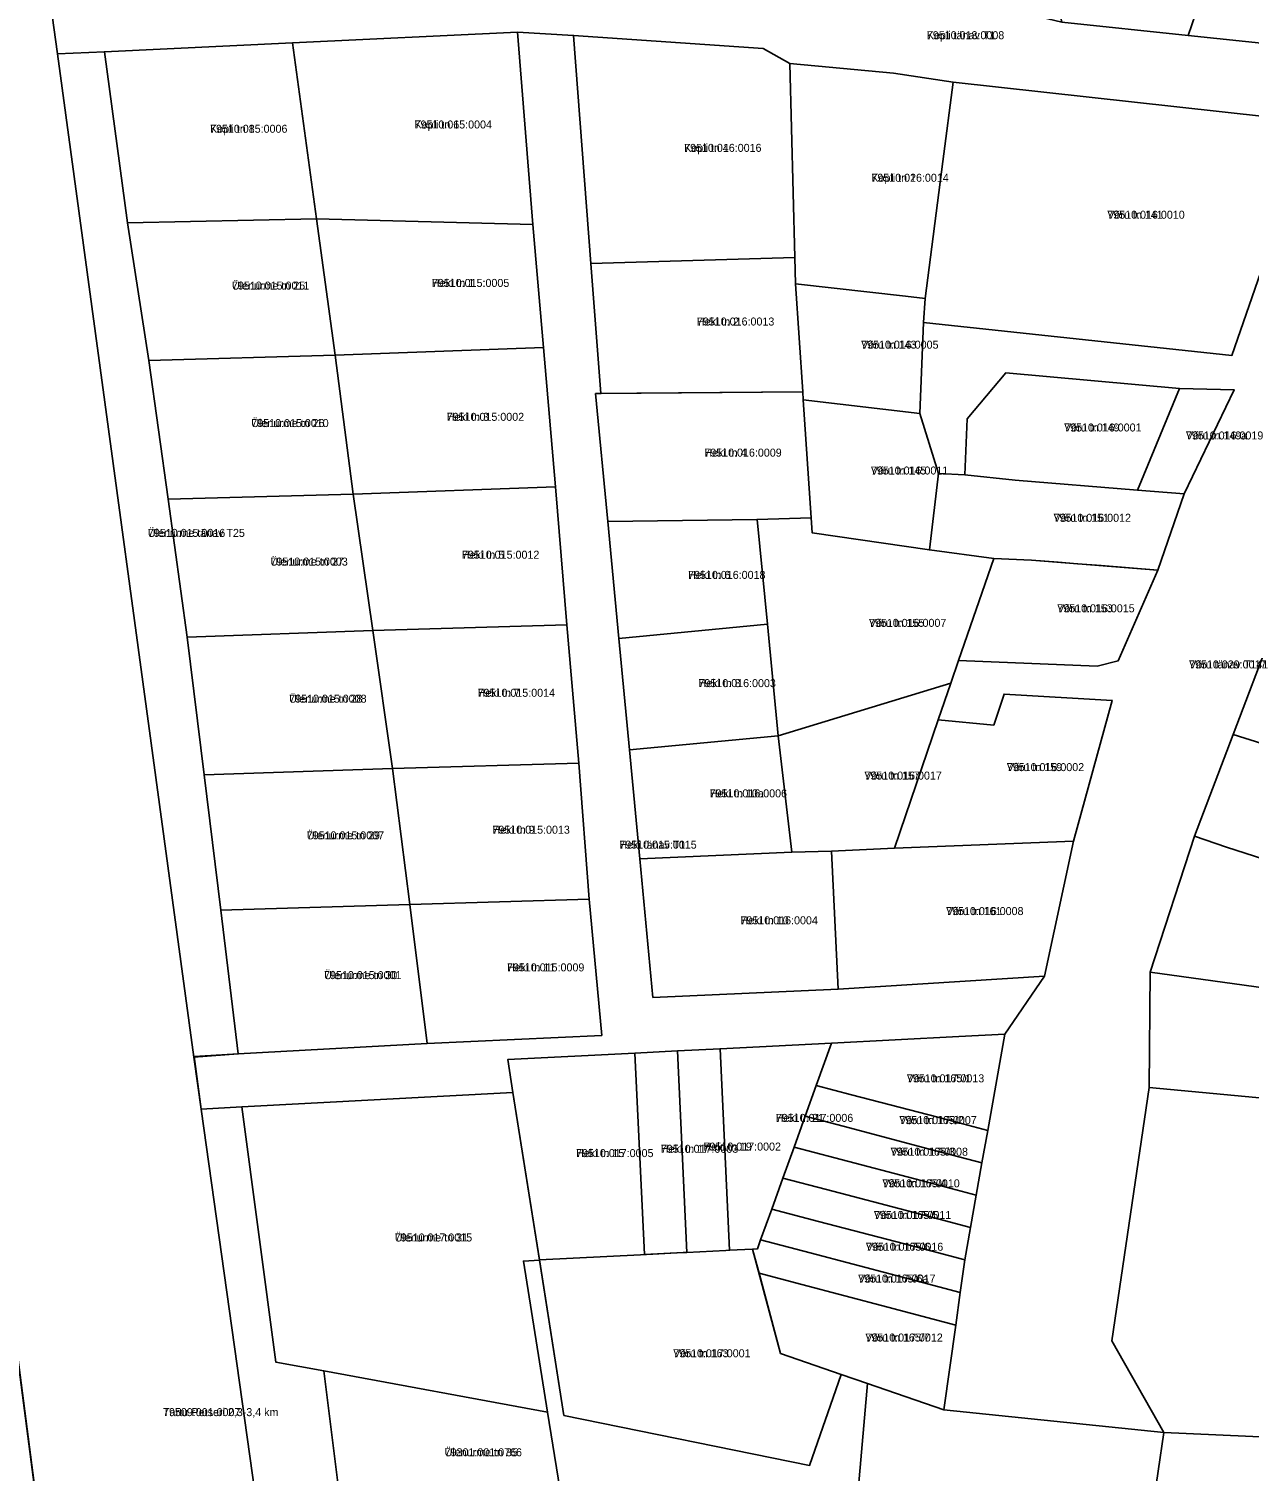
# Model space of a CAD drawing. Extents: x 643847 to 663718, y 6468443 to 6482775.
# Drawn here: x 658757.8 to 658986.5, y 6470500.7 to 6470771 of the extents above; entities that cross this region are included whole.
import ezdxf

# ---------------------------------------------------------------- set-up
doc = ezdxf.new("R2010")
doc.units = 0
for name, color, linetype in [('L_AADRESS', 7, 'Continuous'), ('PIIR', 7, 'Continuous'), ('TUNNUS', 7, 'Continuous')]:
    doc.layers.add(name, color=color, linetype=linetype)

msp = doc.modelspace()

# ---------------------------------------------------------------- linework, layer by layer
at = {"layer": 'PIIR'}
for points in [[(658746.57, 6470967.46), (658748.37, 6470894.81), (658754.88, 6470826.54), (658761.21, 6470780.3), (658763.13, 6470766.29), (658788.68, 6470578.29), (658790.04, 6470568.54), (658806.39, 6470452.3), (658813.68, 6470400.13), (658772.48, 6470401.58), (658771.32, 6470401.59), (658754.4, 6470532.15), (658753.48, 6470542.45), (658748.57, 6470576.12), (658744.35, 6470609.28), (658742.02, 6470624.21), (658737.79, 6470658.27), (658733.34, 6470692.38), (658735.49, 6470707.87), (658715.37, 6470870.27), (658711.74, 6470952.85)], [(658990.76, 6470657.95), (658983.48, 6470638.76), (658976.24, 6470619.67), (658967.89, 6470594.21), (658967.73, 6470572.59), (658960.73, 6470525.08), (658970.5, 6470507.92), (658929.25, 6470512.17), (658931.46, 6470528.06), (658932.31, 6470534.16), (658933.16, 6470540.27), (658934.25, 6470546.35), (658935.32, 6470552.41), (658936.39, 6470558.46), (658937.47, 6470564.52), (658940.67, 6470582.59), (658948.1, 6470593.43), (658953.57, 6470618.75), (658960.81, 6470645.13), (658940.53, 6470646.29), (658938.61, 6470640.5), (658928.18, 6470641.51), (658930.53, 6470648.32), (658931.99, 6470652.57), (658957.95, 6470651.55), (658961.92, 6470652.55), (658969.33, 6470669.51), (658974.27, 6470683.8), (658983.67, 6470703.3), (658973.39, 6470703.57), (658940.84, 6470706.48), (658933.6, 6470697.88), (658933.2, 6470687.37), (658928.25, 6470687.66), (658924.72, 6470698.9), (658925.46, 6470715.92), (658976.23, 6470710.52), (658983.22, 6470709.77), (658998.39, 6470753.53)], [(659005.71, 6470569), (658967.73, 6470572.59), (658967.89, 6470594.21), (659003.14, 6470589.35)]]:
    msp.add_lwpolyline(points, dxfattribs=at)
for points in [[(658956.87, 6470797.9), (658973.43, 6470792.25), (658974.24, 6470794.62), (658982.56, 6470791.78), (658975.03, 6470769.73), (658951.36, 6470772.19), (658950.02, 6470777.84)], [(659003.09, 6470766.8), (658975.03, 6470769.73), (658982.56, 6470791.78), (658983.85, 6470795.56), (659009.88, 6470786.67)], [(658839.94, 6470784.5), (658932.96, 6470776.66), (658951.36, 6470772.19), (658975.03, 6470769.73), (659003.09, 6470766.8), (658998.39, 6470753.53), (658930.96, 6470760.99), (658919.79, 6470762.66), (658900.37, 6470764.47), (658895.41, 6470767.26), (658859.85, 6470769.74), (658849.31, 6470770.31), (658807.18, 6470768.34), (658771.92, 6470766.68), (658763.13, 6470766.29), (658761.21, 6470780.3), (658777.32, 6470781.36), (658804.6, 6470783.22)], [(658807.18, 6470768.34), (658811.64, 6470735.37), (658776.28, 6470734.63), (658771.92, 6470766.68)], [(658852.19, 6470734.27), (658849.31, 6470770.31), (658859.85, 6470769.74), (658863.11, 6470727.01), (658864.98, 6470702.62), (658863.97, 6470702.6), (658866.25, 6470678.65), (658868.33, 6470656.73), (658870.33, 6470635.83), (658872.25, 6470615.41), (658874.72, 6470589.47), (658909.41, 6470591.03), (658948.1, 6470593.43), (658940.67, 6470582.59), (658932.08, 6470582.14), (658908.2, 6470580.91), (658887.31, 6470579.84), (658879.32, 6470579.44), (658871.33, 6470579.03), (658847.52, 6470577.81), (658848.48, 6470571.62), (658797.68, 6470568.93), (658790.04, 6470568.54), (658788.74, 6470578.42), (658797, 6470578.89), (658832.41, 6470580.81), (658865.12, 6470582.34), (658862.79, 6470607.88), (658860.83, 6470633.39), (658858.6, 6470659.27), (658856.45, 6470685.12), (658854.19, 6470711.23)], [(658852.19, 6470734.27), (658811.64, 6470735.37), (658807.18, 6470768.34), (658849.31, 6470770.31)], [(658859.85, 6470769.74), (658895.41, 6470767.26), (658900.37, 6470764.47), (658901.29, 6470728.12), (658863.11, 6470727.01)], [(658776.28, 6470734.63), (658780.22, 6470708.82), (658783.85, 6470682.86), (658787.46, 6470656.98), (658790.61, 6470631.17), (658793.71, 6470605.82), (658797, 6470578.89), (658788.68, 6470578.29), (658763.13, 6470766.29), (658771.92, 6470766.68)], [(658919.79, 6470762.66), (658930.96, 6470760.99), (658929.04, 6470746.11), (658925.74, 6470720.46), (658922.04, 6470720.86), (658901.41, 6470723.16), (658901.29, 6470728.12), (658900.37, 6470764.47)], [(658930.96, 6470760.99), (658998.39, 6470753.53), (658983.22, 6470709.77), (658976.23, 6470710.52), (658925.46, 6470715.92), (658925.74, 6470720.46), (658929.04, 6470746.11)], [(658776.28, 6470734.63), (658811.64, 6470735.37), (658815.17, 6470709.83), (658780.22, 6470708.82)], [(658854.19, 6470711.23), (658815.17, 6470709.83), (658811.64, 6470735.37), (658852.19, 6470734.27)], [(658863.11, 6470727.01), (658901.29, 6470728.12), (658901.41, 6470723.16), (658902.79, 6470702.95), (658864.98, 6470702.62)], [(658925.46, 6470715.92), (658924.72, 6470698.9), (658902.88, 6470701.45), (658902.79, 6470702.95), (658901.41, 6470723.16), (658922.04, 6470720.86), (658925.74, 6470720.46)], [(658780.22, 6470708.82), (658815.17, 6470709.83), (658818.57, 6470683.78), (658783.85, 6470682.86)], [(658856.45, 6470685.12), (658818.57, 6470683.78), (658815.17, 6470709.83), (658854.19, 6470711.23)], [(658965.54, 6470684.53), (658942.59, 6470686.39), (658933.2, 6470687.37), (658933.6, 6470697.88), (658940.84, 6470706.48), (658973.4, 6470703.57)], [(658973.39, 6470703.57), (658983.67, 6470703.3), (658974.27, 6470683.8), (658965.54, 6470684.51)], [(658863.97, 6470702.6), (658902.79, 6470702.95), (658902.88, 6470701.45), (658904.38, 6470679.32), (658894.25, 6470679.05), (658866.25, 6470678.65)], [(658928.25, 6470687.66), (658926.53, 6470673.33), (658904.55, 6470676.53), (658904.38, 6470679.32), (658902.88, 6470701.45), (658924.72, 6470698.9)], [(658969.33, 6470669.51), (658945.69, 6470671.41), (658938.58, 6470671.72), (658926.53, 6470673.33), (658928.25, 6470687.66), (658933.2, 6470687.37), (658942.59, 6470686.39), (658965.54, 6470684.53), (658974.27, 6470683.82)], [(658858.6, 6470659.27), (658822.21, 6470658.21), (658818.57, 6470683.78), (658856.45, 6470685.12)], [(658783.85, 6470682.86), (658818.57, 6470683.78), (658822.21, 6470658.21), (658787.46, 6470656.98)], [(658868.33, 6470656.73), (658866.25, 6470678.65), (658894.25, 6470679.05), (658896.2, 6470659.39)], [(658896.2, 6470659.39), (658894.25, 6470679.05), (658904.38, 6470679.32), (658904.55, 6470676.53), (658926.53, 6470673.33), (658938.58, 6470671.72), (658931.99, 6470652.57), (658930.53, 6470648.32), (658898.19, 6470638.49)], [(658961.92, 6470652.55), (658957.95, 6470651.55), (658931.99, 6470652.57), (658938.58, 6470671.72), (658945.69, 6470671.41), (658950.69, 6470671.01), (658954.26, 6470670.73), (658958.72, 6470670.37), (658969.33, 6470669.51)], [(658787.46, 6470656.98), (658822.21, 6470658.21), (658825.89, 6470632.34), (658790.61, 6470631.17)], [(658860.83, 6470633.39), (658825.89, 6470632.34), (658822.21, 6470658.21), (658858.6, 6470659.27)], [(658868.33, 6470656.73), (658896.2, 6470659.39), (658898.19, 6470638.49), (658870.33, 6470635.83)], [(658990.76, 6470657.95), (658995.52, 6470656.42), (659023.17, 6470647.5), (659022.03, 6470644.2), (659016.46, 6470628.13), (658988.85, 6470637.03), (658983.48, 6470638.76)], [(658900.73, 6470616.69), (658898.19, 6470638.49), (658930.53, 6470648.32), (658928.18, 6470641.51), (658920, 6470617.45), (658908.19, 6470616.85)], [(658953.57, 6470618.75), (658920, 6470617.45), (658928.18, 6470641.51), (658938.61, 6470640.5), (658940.53, 6470646.29), (658960.81, 6470645.13)], [(658870.33, 6470635.83), (658898.19, 6470638.49), (658900.73, 6470616.69), (658872.25, 6470615.41)], [(658983.48, 6470638.76), (658988.85, 6470637.03), (659016.46, 6470628.13), (659014.23, 6470621.5), (659009.8, 6470608.74), (658982.2, 6470617.64), (658976.24, 6470619.67)], [(658862.79, 6470607.88), (658829.14, 6470606.89), (658825.89, 6470632.34), (658860.83, 6470633.39)], [(658790.61, 6470631.17), (658825.89, 6470632.34), (658829.14, 6470606.89), (658793.71, 6470605.82)], [(658976.24, 6470619.67), (658982.2, 6470617.64), (659009.8, 6470608.74), (659003.14, 6470589.35), (658967.89, 6470594.21)], [(658872.25, 6470615.41), (658900.73, 6470616.69), (658908.19, 6470616.85), (658909.41, 6470591.03), (658874.72, 6470589.47)], [(658948.1, 6470593.43), (658909.41, 6470591.03), (658908.19, 6470616.85), (658920, 6470617.45), (658953.57, 6470618.75)], [(658793.71, 6470605.82), (658829.14, 6470606.89), (658832.41, 6470580.81), (658797, 6470578.89)], [(658865.12, 6470582.34), (658832.41, 6470580.81), (658829.14, 6470606.89), (658862.79, 6470607.88)], [(658940.67, 6470582.59), (658937.47, 6470564.52), (658928.09, 6470567.01), (658911.92, 6470571.23), (658905.34, 6470572.98), (658908.2, 6470580.91), (658932.08, 6470582.14)], [(658871.33, 6470579.03), (658873.12, 6470541.27), (658872.42, 6470541.24), (658853.44, 6470540.27), (658848.48, 6470571.62), (658847.52, 6470577.81)], [(658879.32, 6470579.44), (658881.1, 6470541.68), (658880.41, 6470541.64), (658873.12, 6470541.27), (658871.33, 6470579.03)], [(658887.31, 6470579.84), (658889.1, 6470542.09), (658888.4, 6470542.05), (658881.1, 6470541.68), (658879.32, 6470579.44)], [(658908.2, 6470580.91), (658905.34, 6470572.98), (658903.26, 6470567.19), (658901.17, 6470561.4), (658899.09, 6470555.61), (658897, 6470549.81), (658894.91, 6470544.01), (658894.32, 6470542.36), (658893.39, 6470542.3), (658889.1, 6470542.09), (658887.31, 6470579.84)], [(658797.68, 6470568.93), (658848.48, 6470571.62), (658853.44, 6470540.25), (658850.45, 6470540.04), (658854.99, 6470511.73), (658813.03, 6470519.46), (658804.03, 6470521.12)], [(658936.39, 6470558.46), (658926.53, 6470561.05), (658910.39, 6470565.32), (658903.26, 6470567.19), (658905.34, 6470572.98), (658911.92, 6470571.23), (658928.09, 6470567.01), (658937.47, 6470564.52)], [(659005.71, 6470569), (659004.92, 6470560.64), (659014.43, 6470559.74), (659015.22, 6470568.11), (659026.08, 6470567.08), (659021.44, 6470529.27), (659017.75, 6470505.82), (658970.5, 6470507.92), (658960.73, 6470525.08), (658967.73, 6470572.59)], [(658804.03, 6470521.12), (658813.03, 6470519.46), (658817.06, 6470487.49), (658858.62, 6470488.95), (658890, 6470490.35), (658883.39, 6470438.13), (658878.28, 6470439.07), (658806.39, 6470452.3), (658790.04, 6470568.54), (658797.68, 6470568.93)], [(658935.32, 6470552.41), (658924.97, 6470555.13), (658908.83, 6470559.38), (658901.17, 6470561.4), (658903.26, 6470567.19), (658910.39, 6470565.32), (658926.53, 6470561.05), (658936.39, 6470558.46)], [(658934.25, 6470546.35), (658923.4, 6470549.2), (658907.28, 6470553.46), (658899.09, 6470555.61), (658901.17, 6470561.4), (658908.83, 6470559.38), (658924.97, 6470555.13), (658935.32, 6470552.41)], [(658921.84, 6470543.26), (658905.72, 6470547.5), (658897, 6470549.81), (658899.09, 6470555.61), (658907.28, 6470553.46), (658923.4, 6470549.2), (658934.25, 6470546.35), (658933.16, 6470540.27)], [(658897, 6470549.81), (658905.72, 6470547.5), (658921.84, 6470543.26), (658933.16, 6470540.27), (658932.31, 6470534.16), (658920.28, 6470537.33), (658904.17, 6470541.57), (658894.91, 6470544.01)], [(658893.39, 6470542.29), (658894.31, 6470542.34), (658894.91, 6470544.01), (658904.17, 6470541.57), (658920.28, 6470537.33), (658932.31, 6470534.16), (658931.46, 6470528.05), (658918.72, 6470531.4), (658902.62, 6470535.64), (658894.61, 6470537.76)], [(658904.09, 6470501.75), (658858.04, 6470511.13), (658853.44, 6470540.27), (658872.42, 6470541.24), (658880.41, 6470541.64), (658881.1, 6470541.68), (658888.4, 6470542.05), (658889.1, 6470542.09), (658893.39, 6470542.3), (658898.66, 6470522.74), (658909.99, 6470518.82)], [(658912.69, 6470491.37), (658890, 6470490.35), (658858.62, 6470488.95), (658854.99, 6470511.73), (658850.45, 6470540.04), (658853.44, 6470540.25), (658858.04, 6470511.13), (658904.09, 6470501.75), (658909.99, 6470518.82), (658914.95, 6470517.11)], [(658929.25, 6470512.17), (658914.95, 6470517.11), (658909.99, 6470518.82), (658898.66, 6470522.74), (658894.61, 6470537.78), (658902.62, 6470535.66), (658918.72, 6470531.42), (658931.46, 6470528.06)], [(658754.31, 6470532.24), (658771.32, 6470401.57), (658652.18, 6470398.91), (658647.27, 6470431.68), (658699.05, 6470440.41), (658694.89, 6470480.89), (658641.17, 6470477.78), (658632.97, 6470526.78)], [(658858.62, 6470488.95), (658817.06, 6470487.49), (658813.03, 6470519.46), (658854.99, 6470511.73)], [(658912.69, 6470491.37), (658914.95, 6470517.11), (658929.25, 6470512.17), (658970.5, 6470507.92), (658968.33, 6470493.45), (658959.37, 6470433.88), (658958.07, 6470399.38), (658956.21, 6470350.25), (658929.13, 6470182.89), (658908.15, 6470192.43), (658907.56, 6470204.71), (658907.05, 6470227.38), (658906.76, 6470240.09), (658901.62, 6470307.58), (658910.37, 6470376.7), (658914.67, 6470410.49), (658917.39, 6470431.87)], [(659015.01, 6470488.43), (659038.14, 6470485.66), (659052.34, 6470484.05), (659083, 6470486.1), (659081.79, 6470476.89), (659005.22, 6470476.43), (658992.85, 6470488.52), (658968.33, 6470493.45), (658970.5, 6470507.92), (659017.75, 6470505.82)]]:
    msp.add_lwpolyline(points, close=True, dxfattribs=at)

# ---------------------------------------------------------------- texts
at = {"layer": 'L_AADRESS'}
for s, p in [('Kopli tänav T1', (658926.06, 6470769.02)), ('Kopli tn 8', (658791.72, 6470751.49)), ('Kopli tn 6', (658830.05, 6470752.29)), ('Kopli tn 4', (658880.57, 6470747.91)), ('Kopli tn 2', (658915.66, 6470742.31)), ('Võru tn 141', (658959.88, 6470735.38)), ('Ülenurme tn 25', (658795.83, 6470722.1)), ('Heki tn 1', (658833.3, 6470722.6)), ('Heki tn 2', (658882.97, 6470715.37)), ('Võru tn 143', (658913.74, 6470711.03)), ('Ülenurme tn 26', (658799.45, 6470696.34)), ('Heki tn 3', (658836.08, 6470697.51)), ('Võru tn 149', (658951.79, 6470695.51)), ('Võru tn 149a', (658974.61, 6470694.02)), ('Heki tn 4', (658884.35, 6470690.8)), ('Võru tn 145', (658915.57, 6470687.45)), ('Võru tn 151', (658949.81, 6470678.59)), ('Ülenurme tänav T25', (658780.07, 6470675.76)), ('Ülenurme tn 27', (658803.03, 6470670.38)), ('Heki tn 5', (658838.93, 6470671.67)), ('Heki tn 6', (658881.31, 6470667.89)), ('Võru tn 153', (658950.5, 6470661.63)), ('Võru tn 155', (658915.21, 6470658.9)), ('Võru tänav T141', (658975.2, 6470651.11)), ('Ülenurme tn 28', (658806.55, 6470644.69)), ('Heki tn 7', (658841.87, 6470645.8)), ('Heki tn 8', (658883.26, 6470647.61)), ('Võru tn 159', (658941.04, 6470631.87)), ('Võru tn 157', (658914.36, 6470630.28)), ('Heki tn 10a', (658885.35, 6470626.95)), ('Ülenurme tn 29', (658809.84, 6470619.08)), ('Heki tn 9', (658844.65, 6470620.14)), ('Heki tänav T1', (658868.42, 6470617.34)), ('Võru tn 161', (658929.67, 6470604.89)), ('Heki tn 10', (658891.13, 6470603.16)), ('Heki tn 11', (658847.37, 6470594.34)), ('Ülenurme tn 30', (658813.09, 6470592.89)), ('Võru tn 165/1', (658922.31, 6470573.55)), ('Heki tn 21', (658897.76, 6470566.14)), ('Võru tn 165/2', (658920.91, 6470565.72)), ('Heki tn 15', (658860.32, 6470559.54)), ('Heki tn 17', (658876.21, 6470560.35)), ('Heki tn 19', (658884.21, 6470560.76)), ('Võru tn 165/3', (658919.26, 6470559.8)), ('Võru tn 165/4', (658917.72, 6470553.88)), ('Võru tn 165/5', (658916.13, 6470547.94)), ('Ülenurme tn 31', (658826.34, 6470543.73)), ('Võru tn 165/6', (658914.63, 6470541.99)), ('Võru tn 165/6a', (658913.18, 6470536.03)), ('Võru tn 165/7', (658914.54, 6470524.98)), ('Võru tn 163', (658878.52, 6470522.03)), ('Tartu-Petseri 2,3-3,4 km', (658782.91, 6470511)), ('Ülenurme tn 35', (658835.68, 6470503.48))]:
    msp.add_text(s, height=1.5, dxfattribs=at).set_placement(p)
at = {"layer": 'TUNNUS'}
for s, p in [('79510:013:0008', (658926.06, 6470769.02)), ('79510:015:0006', (658791.72, 6470751.49)), ('79510:015:0004', (658830.05, 6470752.29)), ('79510:016:0016', (658880.57, 6470747.91)), ('79510:016:0014', (658915.66, 6470742.31)), ('79510:016:0010', (658959.88, 6470735.38)), ('79510:015:0011', (658795.83, 6470722.1)), ('79510:015:0005', (658833.3, 6470722.6)), ('79510:016:0013', (658882.97, 6470715.37)), ('79510:016:0005', (658913.74, 6470711.03)), ('79510:015:0010', (658799.45, 6470696.34)), ('79510:015:0002', (658836.08, 6470697.51)), ('79510:016:0001', (658951.79, 6470695.51)), ('79510:016:0019', (658974.61, 6470694.02)), ('79510:016:0009', (658884.35, 6470690.8)), ('79510:016:0011', (658915.57, 6470687.45)), ('79510:016:0012', (658949.81, 6470678.59)), ('79510:015:0016', (658780.07, 6470675.76)), ('79510:015:0003', (658803.03, 6470670.38)), ('79510:015:0012', (658838.93, 6470671.67)), ('79510:016:0018', (658881.31, 6470667.89)), ('79510:016:0015', (658950.5, 6470661.63)), ('79510:016:0007', (658915.21, 6470658.9)), ('79510:029:0017', (658975.2, 6470651.11)), ('79510:015:0014', (658841.87, 6470645.8)), ('79510:016:0003', (658883.26, 6470647.61)), ('79510:015:0008', (658806.55, 6470644.69)), ('79510:016:0002', (658941.04, 6470631.87)), ('79510:016:0017', (658914.36, 6470630.28)), ('79510:016:0006', (658885.35, 6470626.95)), ('79510:015:0007', (658809.84, 6470619.08)), ('79510:015:0013', (658844.65, 6470620.14)), ('79510:015:0015', (658868.42, 6470617.34)), ('79510:016:0008', (658929.67, 6470604.89)), ('79510:016:0004', (658891.13, 6470603.16)), ('79510:015:0009', (658847.37, 6470594.34)), ('79510:015:0001', (658813.09, 6470592.89)), ('79510:017:0013', (658922.31, 6470573.55)), ('79510:017:0006', (658897.76, 6470566.14)), ('79510:017:0007', (658920.91, 6470565.72)), ('79510:017:0005', (658860.32, 6470559.54)), ('79510:017:0003', (658876.21, 6470560.35)), ('79510:017:0002', (658884.21, 6470560.76)), ('79510:017:0008', (658919.26, 6470559.8)), ('79510:017:0010', (658917.72, 6470553.88)), ('79510:017:0011', (658916.13, 6470547.94)), ('79510:017:0015', (658826.34, 6470543.73)), ('79510:017:0016', (658914.63, 6470541.99)), ('79510:017:0017', (658913.18, 6470536.03)), ('79510:017:0012', (658914.54, 6470524.98)), ('79510:017:0001', (658878.52, 6470522.03)), ('79509:001:0007', (658782.91, 6470511)), ('79301:001:0766', (658835.68, 6470503.48))]:
    msp.add_text(s, height=1.5, dxfattribs=at).set_placement(p)

doc.saveas('drawing.dxf')
